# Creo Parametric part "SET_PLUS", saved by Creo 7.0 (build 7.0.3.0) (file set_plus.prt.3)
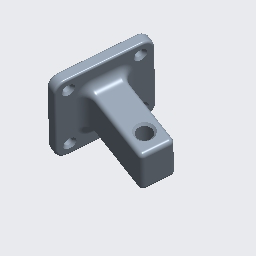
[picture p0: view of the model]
Units: millimeter Kilogram Sec (mmKs); MM, KILOGRAM, SECS

Created from: XX_SOLID_PART_MMKS_ABS.PRT

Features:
  1. coordinate system
  2. datum plane "RIGHT"
  3. datum plane "TOP"
  4. datum plane "FRONT"
  5. extrusion "Extrude 1"
  6. extruded cut "Extrude 2"
  7. extrusion "Extrude 3"
  8. extruded cut "Extrude 4"
  9. round "Round 1"
  10. round "Round 2"
  11. round "Round 3"
  12. chamfer "Chamfer 1"

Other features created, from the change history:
  round "Round 1"
  round "Round 2"
  round "Round 3"
  chamfer "Chamfer 1"
  round "Round 4"
  chamfer "Chamfer 2"
  chamfer "Chamfer 3"
  extruded cut "Extrude 5"
  round "Round 5"
  round "Round 6"
  round "Round 7"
